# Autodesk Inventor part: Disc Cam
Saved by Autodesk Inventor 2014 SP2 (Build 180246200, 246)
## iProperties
Created: 2016-02
Part Number: Disc Cam
Material: Stainless Steel, Austenitic
Document SubType Name: Modeling
Designer: User
Manufacturer: Standard
Standards Organization: Custom
Density: 1 g/cm^3
Appearance: Steel
CustomPartVersion: 1
Author: User
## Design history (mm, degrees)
sketch "Main Sketch"
  geometry: 60 further points
  constraints: 60 other
extrude "Cam" new body sketch "Main Sketch" taper "d1" = 0 deg; distance "da_bv" = 10
body "Solid1"
other parameters: "d2" = 0, "d3" = 0
